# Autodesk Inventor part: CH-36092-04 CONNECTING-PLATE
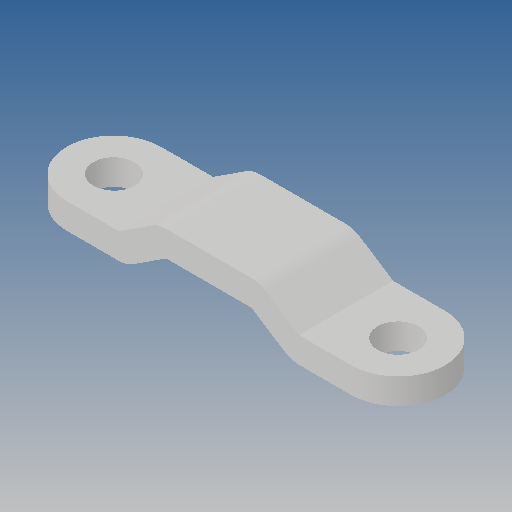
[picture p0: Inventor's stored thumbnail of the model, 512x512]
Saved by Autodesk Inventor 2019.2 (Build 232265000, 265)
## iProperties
Created: 2012-09
Part Number: CH-36092-04 CONNECTING-PLATE
Material: Ogólny
Document SubType Name: Modeling
Designer: CADENGINEERING4
Density: 1 g/cm^3
Appearance: Domyślna
Author: CADENGINEERING4
Revision Number: ÈÎºÎ
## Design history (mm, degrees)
feature "ÇÐ³ý-À­Éì1"
node "Bryła1"
